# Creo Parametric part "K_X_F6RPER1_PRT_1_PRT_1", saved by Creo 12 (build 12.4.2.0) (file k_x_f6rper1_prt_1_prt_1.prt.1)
Units: Custom; MM, KILOGRAM, SECS

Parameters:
  PTC_WM_ITERATION = "0"
  PTC_WM_VERSION = "-.0"
  PTC_WM_LIFECYCLE_STATE = "In Work"
  PTC_WM_LIFECYCLE = "MO_CADDocument"
  PTC_WM_CREATED_BY = "Maximilian Roepper (Z0017RMS: MO)"
  PTC_WM_CREATED_ON = "18-Sep-26 11:36:42 AM"
  PTC_WM_MODIFIED_BY = "Maximilian Roepper (Z0017RMS: MO)"
  PTC_WM_MODIFIED_ON = "18-Sep-26 11:36:46 AM"
  PDMLINKNUMBER = "PDM000071455269"
  PTC_WM_NAME = "k_x_f6rper1_prt_1_prt_1.prt"
  PTC_WM_NUMBER = "PDM000071455269"

Other parameters: WEIGHT, WEIGHT_FACTOR, WEIGHT_ADD, _MASS_TEMP, _DIFF_TEMP, MC_ERRORS, SUPPLIER

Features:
  1. coordinate system
  2. datum plane "PRT_YZ"
  3. datum plane "PRT_XY"
  4. datum plane "PRT_XZ"
  5. coordinate system
  6. datum axis
  7. datum axis
  8. datum axis
  9. coordinate system
  10. imported feature

Other named items: PRT, SIEMENS_MO, DRW_VIEW_ORG, PRT_X, PRT_Y, PRT_Z, CS0, ROUGH_GROB

Layers: 00_STD_CSYS-KSYS, 01_STD_PLANES-EBENEN, 02_STD_AXES-ACHSEN, 03_STD_CSYS-KSYS, 24_IMPORT_FEAT-IMPORT_KE

Surfaces: 24 cylinder, 6 plane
